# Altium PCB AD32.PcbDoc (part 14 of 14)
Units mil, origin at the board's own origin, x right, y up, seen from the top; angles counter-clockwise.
Board outline 7007.87 x 4368.85 mil, 12 copper layers (Top Layer, Int1 (GND), Int2 (AVDD), Int3 (DVDD), Int4 (GND), Int5 (ST), Int6 (SB), Int8 (AGND), Int7 (AVCC), Int9 (VCCA), Int10 (GND), Bottom Layer), stack 60.136 mil thick; 1350 components, 880 nets, 4712 pads, 2835 vias.
Unrouted connection lines stored in the file: 19.
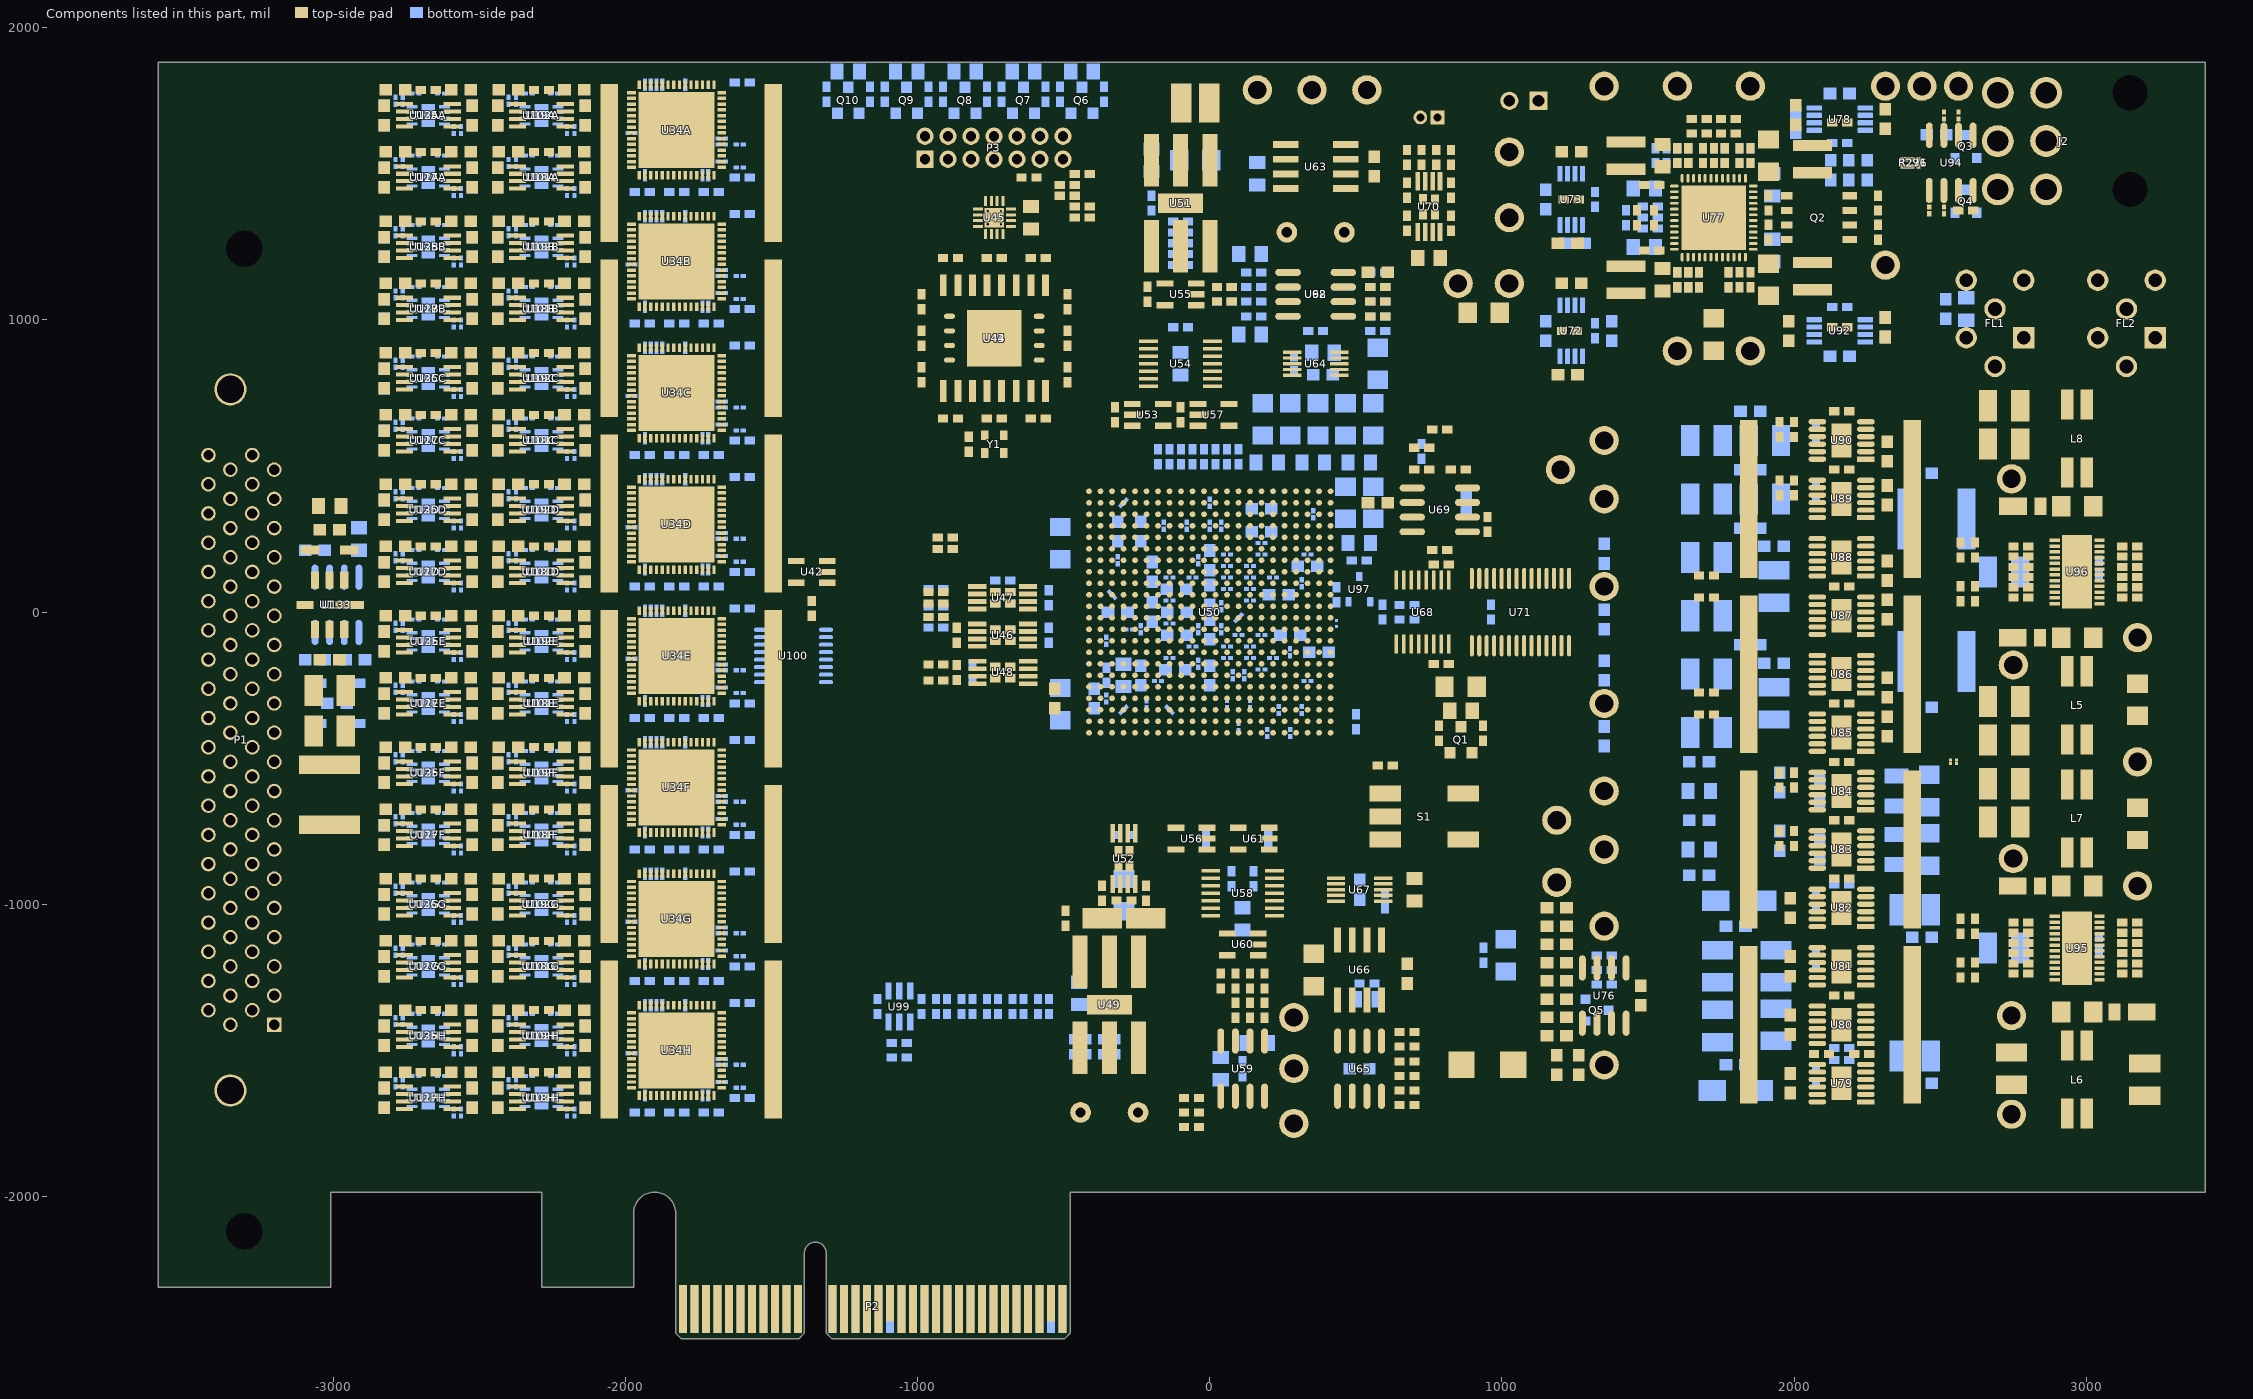
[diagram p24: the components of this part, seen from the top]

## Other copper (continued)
Int3 (DVDD) (plane layer: these items are gaps in the copper):
  lines w20: -2862.5,1882.5 -2862.5,962.5 -3006.25,818.75 -3006.25,-693.75 -2862.5,-837.5 -2862.5,-1787.5 -2850,-1800 -2100,-1800 -1925,-1975 -1812.5,-1975 -800,-1975 -625,-1800 621.06,-1800 725,-1696.06 846.06,-1575 1047.44,-1575 1112.7,-1640.26 1272.44,-1800 3237.5,-1800 3262.5,-1775 3262.5,775 3175,862.5 3175,1237.5 2970,1237.5 2970,781.25 2725,781.25 ; -1175,1880 -1525,1880 -1525,-1362.5 1031.25,-1362.5 1143.75,-1475 1462.5,-1475 1462.5,175 1275,362.5 1275,412.5 1506.25,643.75 1643.75,781.25 2450,781.25 ; 915.35,840.35 915.35,1412.5 1072.5,1412.5 1200,1412.5 1200,1275 1256.25,1275 1425,1275 1425,1437.5 ; 2345,-1800 2325,-1800 2450,-1800 2450,-800 ; 2375,1882.5 2375,1618.75 2582.43,1618.75 2637.5,1563.68 2637.5,1501.81 2637.5,1237.5 2725,1237.5 2725,781.25 ; 2450,700 2450,781.25 ; 1425,1437.5 1587.5,1437.5 1587.5,1162.5 1023.62,1162.5 1023.62,797.24 669.29,442.91 511.81,442.91 511.81,492.13 570.87,492.13 915.35,836.61 679.13,836.61 -19.68,137.8 -19.68,-136.81 20.67,-177.17 177.17,-177.17 216.54,-137.8 216.54,137.8 378.74,300 851.18,300 1149.61,598.43 1149.61,933.07 1266.54,1050 1882.5,1050 1902.5,1030 2070,862.5 2225,862.5 2275,912.5 2275,1472.5 2160,1587.5 1425,1587.5 1425,1437.5 ; 2450,-800 2450,-800 ; 2450,-800 2450,-650 2450,781.25 ; 2450,781.25 2725,781.25
Int2 (AVDD) (plane layer: these items are gaps in the copper):
  lines w20: -2862.5,-1287.5 -1975,-1287.5 ; -2862.5,-837.5 -1975,-837.5 ; -2862.5,-387.5 -1975,-387.5 ; -2862.5,62.5 -1975,62.5 ; -2862.5,512.5 -1975,512.5 ; -2862.5,962.5 -1975,962.5 ; -2862.5,1412.5 -1975,1412.5 ; -2862.5,1882.5 -2862.5,-1787.5 -2850,-1800 -1975,-1800 ; -1975,1882.5 -1975,-1800 ; -1525,1882.5 -1525,-1362.5 287.5,-1362.5 343.75,-1306.25 368.75,-1306.25 425,-1362.5 1031.25,-1362.5 1143.75,-1475 1462.5,-1475 1462.5,375 1275,562.5 1275,612.5 1443.75,781.25 1771.88,781.25 2000,781.25 2000,-800 2000,-1800 ; -62.5,-1800 -50,-1800 ; 954.72,-1985.53 954.72,-1575 ; 1998.18,-650 2000,-650 ; 2375,1882.5 2375,1237.5 2725,1237.5 2725,781.25 ; 2450,-512.5 3262.5,-512.5 ; -1975,-1893.75 -1975,-1800 ; -1975,-1893.75 -1975,-1893.75 ; -1975,-1893.75 -1893.75,-1975 -800.78,-1975 -625.78,-1800 621.06,-1800 725,-1696.06 725,-1687.5 733.56,-1687.5 846.06,-1575 1047.44,-1575 1112.5,-1640.06 1272.44,-1800 3237.5,-1800 3262.5,-1775 3262.5,775 3175,862.5 3175,1237.5 2970,1237.5 2970,781.25 2725,781.25 ; 2450,-1800 2450,781.25 2725,781.25 ; 2450,-1800 2450,-1800 ; 620.08,206.69 944.88,-118.11 1092.52,-118.11 1250,39.37 1250,206.69 935.04,521.65 935.04,1210.63 767.72,1210.63 767.72,442.91 620.08,295.28 620.08,206.69
Int4 (GND) (plane layer: these items are gaps in the copper):
  lines w20: -3615,1037.5 -3062.5,1037.5 ; -2100,1882.5 -2100,-1800 -1925,-1975 ; 2375,-1800 2450,-1800 ; 2375,1612.5 2375,1875 2187.5,1875 1900,1587.5 1793.13,1587.5 1212.5,1587.5 1112.5,1487.5 1112.5,805 995,687.5 762.5,687.5 687.5,612.5 687.5,437.5 565,315 452.5,315 422.5,285 422.5,85 350,12.5 137.5,12.5 100,-25 100,-100 100,-125 137.5,-162.5 350,-162.5 412.5,-225 907.19,-225 1031.25,-349.06 1031.25,-1362.5 1143.75,-1475 1175,-1475 1175,-1000 1175,-921.18 1175,-305.31 1475,-5.31 1475,525 1650,700 2062.5,700 2275,912.5 2275,1200 2375,1300 2375,1618.75 2582.43,1618.75 2603.59,1597.59 2637.5,1563.68 2637.5,1237.5 2725,1237.5 2725,781.25 2970,781.25 2970,925.08 2970,1237.5 3175,1237.5 3175,862.5 3262.5,775 ; 3417.5,775 3262.5,775 ; -1925,-1975 -1925,-1975 ; -1925,-1975 -1831.63,-1975 -800,-1975 -625,-1800 621.06,-1800 725,-1696.06 846.06,-1575 1047.44,-1575 1135.83,-1663.39 1272.44,-1800 3237.5,-1800 3262.5,-1775 3262.5,775
Int7 (AVCC) (plane layer: these items are gaps in the copper):
  lines w20: -2100,1882.5 -2100,-1800 -912.5,-1800 -725,-1612.5 550,-1612.5 1158.56,-1003.94 1593.75,-1003.94 1593.75,-1800 2325,-1800 ; -1900,-1975 -800,-1975 -625,-1800 621.06,-1800 725,-1696.06 846.06,-1575 1047.44,-1575 1272.44,-1800 2450,-1800 2450,-542.5 2450,-512.5 2450,781.25 ; -1175,1880 -1175,-1362.5 -847.97,-1362.5 -537.5,-1362.5 431.25,-1362.5 1275,-518.75 1275,-287.5 1462.5,-100 1462.5,105 1462.5,781.25 2450,781.25 ; 2375,-1800 3237.5,-1800 3262.5,-1775 3262.5,775 3175,862.5 3175,1237.5 2970,1237.5 2970,781.25 2725,781.25 ; 2375,1882.5 2375,1237.5 2725,1237.5 2725,781.25 ; 2450,700 2450,781.25 ; 2725,820.77 2725,781.25 ; 2450,781.25 2725,781.25
Int9 (VCCA) (plane layer: these items are gaps in the copper):
  lines w20: -2100,1882.5 -2100,-1800 -912.5,-1800 -725,-1612.5 550,-1612.5 1158.56,-1003.94 1593.75,-1003.94 1593.75,-1800 1272.44,-1800 ; -1900,-1975 -1895,-1975 ; -1175,1880 -1175,-1362.5 -831.25,-1362.5 -537.5,-1362.5 431.25,-1362.5 1462.5,-331.25 1462.5,-125 1275,62.5 1275,112.5 1462.5,300 1462.5,442.5 1462.5,781.25 1924.38,781.25 2450,781.25 ; 954.72,-1985.53 954.72,-1575 955.26,-1575 ; 2375,1882.5 2375,1237.5 2725,1237.5 2725,781.25 ; -1895,-1975 -1895,-1975 ; -1895,-1975 -800,-1975 -625,-1800 ; -625,-1800 621.06,-1800 846.06,-1575 1041.87,-1575 1047.44,-1575 ; -625,-1800 622.05,-1800 847.05,-1575 1047.44,-1575 ; 1047.44,-1575 1272.44,-1800 ; 1047.44,-1575 1272.44,-1800 ; 1272.44,-1800 2450,-1800 ; 2450,-1800 2450,781.25 ; 2450,-1800 3237.5,-1800 3262.5,-1775 3262.5,775 3175,862.5 3175,1237.5 2970,1237.5 2970,781.25 2725,781.25 ; 2450,781.25 2725,781.25
Int1 (GND) (plane layer: these items are gaps in the copper):
  lines w20: -1925,-1975 -800,-1975 -625,-1800 621.06,-1800 725,-1696.06 846.06,-1575 1047.44,-1575 1112.5,-1640.06 1272.44,-1800 3237.5,-1800 3262.5,-1775 3262.5,775 ; 2375,1875 2375,1618.75 2582.43,1618.75 2637.5,1563.68 2637.5,1437.5 2637.5,1237.5 2725,1237.5 2725,781.25 2970,781.25 2970,1237.5 3175,1237.5 3175,862.5 3262.5,775 ; 3262.5,775 3262.5,775
Int10 (GND) (plane layer: these items are gaps in the copper):
  lines w20: -1925,-1975 -800,-1975 -625,-1800 621.89,-1800 846.89,-1575 1047.24,-1575 1272.24,-1800 3237.5,-1800 3262.5,-1775 3262.5,775 3175,862.5 3175,1237.5 2970,1237.5 2970,781.25 2725,781.25 2725,1237.5 2375,1237.5 2375,1882.5

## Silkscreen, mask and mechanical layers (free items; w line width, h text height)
Top Overlay:
  lines w3.94: 1515,1752.5 1547.5,1752.5 1625,1675 1643.75,1656.25 ; 1943.75,1763.75 1913.75,1763.75 1825,1675 1818.75,1668.75 1806.25,1656.25 ; 1643.75,1656.25 1637.5,1656.25 1643.75,1662.5 1643.75,1656.25 ; 1806.25,1656.25 1812.5,1656.25 1806.25,1662.5 1806.25,1656.25
  lines w10: -2087.5,1882.5 -2087.5,-1800 -2062.5,-1800 -1256.25,-1800 -1175,-1718.75 -1175,1880 ; -1900,-1975 -800,-1975 -625,-1800 621.06,-1800 810.04,-1611.02 ; 968.75,1882.5 968.75,831.25 1018.75,781.25 2375,781.25 ; 1085,-1612.5 1272.5,-1800 1593.75,-1800 ; 1593.75,-1787.5 1593.75,-1800 ; 1593.75,781.25 1593.75,-1800 ; 2325,-512.5 3262.5,-512.5 ; 2375,1882.5 2375,1865 2375,781.25 ; 2543.75,-1787.5 2543.75,781.25 ; 1593.75,-1800 3237.5,-1800 3262.5,-1775 3262.5,781.25 2375,781.25
  text "D2300400" at -3573.23,1661.61 h30
  text "LIGO ADC32" at -3573.23,1606.25 h30
  text "rev 2" at -3573.23,1547.54 h30
Bottom Overlay:
  region: -275.59,1417.32 -1422.24,1417.32 -1422.24,1112.5 -275.59,1112.5
  lines w5: -451.77,356.3 -440.94,356.3 -367.13,430.12 -367.13,481.3 ; -404.04,393.21 -404.04,166.83 -345.47,108.27 -232.28,108.27 ; -349.41,-521.65 -300.2,-472.44 -132.87,-472.44 ; -243.11,97.44 -232.28,108.27 ; -242.62,97.93 -232.28,108.27 ; -177.17,-472.44 -177.17,-312.06 -118.11,-253.01 -118.11,-226.25 ; -127.95,-236.09 -118.11,-226.25 ; -108.27,-236.22 -118.11,-226.38 -118.11,-226.25 ; 156.25,-48.13 146.25,-38.13 ; 156.25,-28.14 146.25,-38.13 ; 537.4,-439.96 537.4,-234.25 632.87,-138.78 817.8,-138.78 ; 581.66,-190 562.99,-171.33 562.99,-118.62 482.51,-38.13 146.25,-38.13 ; -243.11,119.09 -232.28,108.27 ; -243.11,119.09 -243.11,119.09 ; -243.11,119.09 -232.28,108.27 ; -232.28,108.27 -232.28,108.27 ; -232.28,108.27 -232.28,108.27
  text "SN" at -277.64,1425.28 h30
Mechanical 1:
  lines w3.94: -3600,-2310.33 -3600,1888.48 3407.87,1888.48 3407.87,-1985.53 -1029.13,-1985.53 -1029.13,-2467.82 -1048.82,-2487.5 -1292.91,-2487.5 -1312.6,-2467.82 -1312.6,-2194.19 ccw(c-1350,-2194.19) -1387.4,-2194.19 -1387.4,-2467.82 -1407.09,-2487.5 -1808.66,-2487.5 -1828.35,-2467.82 -1828.35,-2057.38 ccw(c-1900.2,-2057.38) -1972.05,-2057.38 -1972.05,-2310.33 -2287.01,-2310.33 -2287.01,-1985.53 -3009.45,-1985.53 -3009.45,-2310.33 -3600,-2310.33
Mechanical5:
  lines w10: -433.07,74.8 -433.07,433.07 118.11,433.07 ; -236.22,433.07 -236.22,314.96 -196.85,314.96 -196.85,157.48 -157.48,157.48 0,157.48 0,118.11 ; 78.74,118.11 78.74,354.33 118.11,354.33 118.11,433.07 ; -433.07,-157.48 -433.07,-433.07 -39.37,-433.07 0,-433.07 ; -433.07,-157.48 -354.33,-157.48 ; -433.07,-157.48 -433.07,78.74 -236.22,78.74 -236.22,39.37 0,39.37 ; -354.33,-157.48 -354.33,-157.48 ; -354.33,-157.48 -354.33,-196.85 -314.96,-196.85 0,-196.85 ; 0,-433.07 433.07,-433.07 433.07,118.11 ; 0,-433.07 0,-196.85 ; 0,-196.85 0,-157.48 0,-3.94 0,39.37 ; 0,39.37 0,118.11 ; 0,118.11 216.54,118.11 433.07,118.11 ; 118.11,433.07 433.07,433.07 433.07,118.11
  text "BANK34" at 78.78,245 h30
  text "BANK13" at -151.22,241.25 h30
  text "BANK14" at -394.97,173.75 h30
  text "BANK15" at -316.22,-77.5 h30
  text "BANK35" at 131.28,-111.25 h30
  text "BANK16" at -291.22,-317.5 h30
Mechanical7:
  lines w3.94: -3600,-1946.16 -3600,-2310.33 -3009.45,-2310.33 -3009.45,-1985.53 -2287.01,-1985.53 -2287.01,-2174.51 -1972.05,-2174.51 -1972.05,-2057.38 cw(c-1900.2,-2057.38) -1828.35,-2057.38 -1828.35,-1946.16 ; -3590.16,-1995.37 -1818.5,-1995.37
PCI-SIG Dimensions:
  lines w3.94: -3645,-1413.25 -3810.75,-1413.25 -3810.77,-1444.78 -3826.52,-1444.78 -3858.01,-1413.29 -3858.01,638.29 -3826.52,669.78 -3810.77,669.78 -3810.77,638.25 -3641.52,638.25 -3641.48,638.29 -3641.48,870.57 ; -3641.46,-1645.57 -3176.91,-1645.57 -3176.91,870.57 ; -3641.46,-1642.5 -3641.46,-1413.25 ; -3641.47,870.56 -3176.9,870.56
Mechanical15:
  lines w1.97: -3869.8,-1649.51 -3172.95,-1649.51 -3172.95,874.51 -3869.8,874.51 -3869.8,-1649.51
  lines w3.94: -3359.69,-387.5 -3320.32,-387.5 ; -3340,-407.19 -3340,-367.82

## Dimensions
-3600,-2487.5 to -3600,1888.48 on PCI-SIG Dimensions
-3600,-2310.33 to -3600,1888.48 on PCI-SIG Dimensions
-3600,1888.48 to 3407.87,1902.26 on PCI-SIG Dimensions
